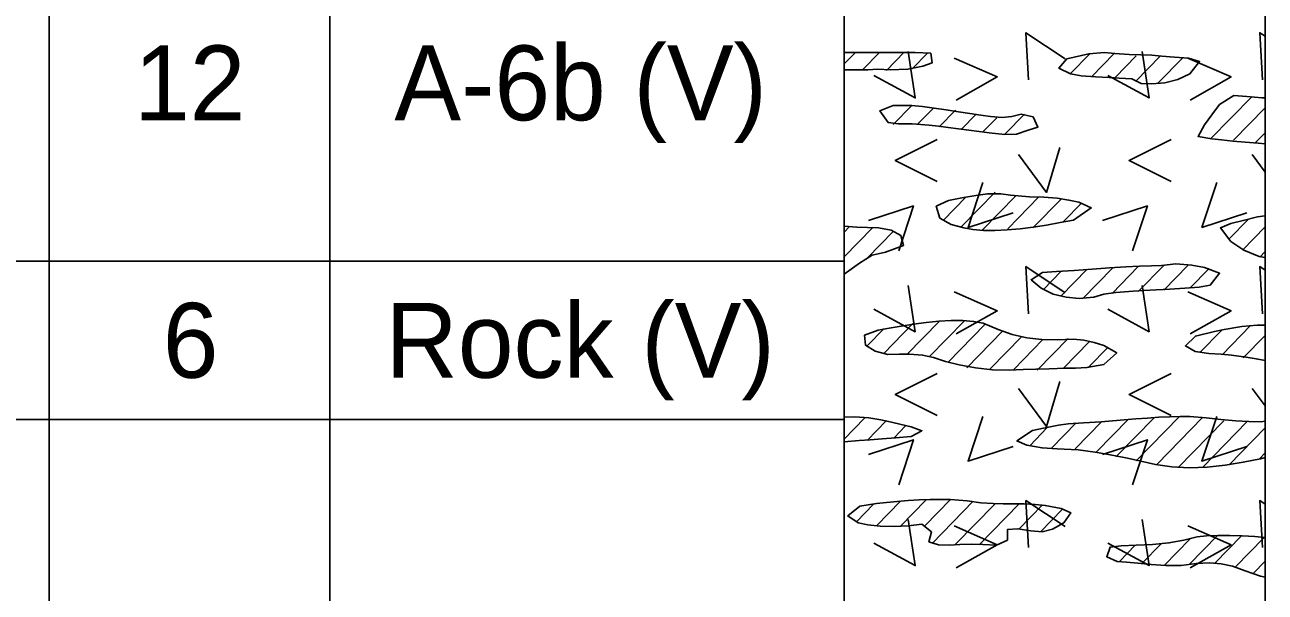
# Model space of a CAD drawing. Extents: x 0 to 0.833, y -0.32 to 0.608.
# Drawn here: x 0.7228 to 0.8333, y 0.0658 to 0.1163 of the extents above; entities that cross this region are included whole.
import ezdxf

# ---------------------------------------------------------------- set-up
doc = ezdxf.new("R2010")
doc.units = 0

msp = doc.modelspace()

# ---------------------------------------------------------------- linework, layer by layer
for points in [[(0, -0.32004), (0.83333, -0.32004), (0.83333, 0.60833), (0, 0.60833)], [(0.79583, 0.1123), (0.79676, 0.11229), (0.79792, 0.1123), (0.79882, 0.11234), (0.79992, 0.1123), (0.80151, 0.11234), (0.80282, 0.1126), (0.80367, 0.11292), (0.80354, 0.11376), (0.80216, 0.11384), (0.79583, 0.11384)], [(0.81822, 0.11165), (0.81944, 0.11159), (0.82033, 0.11155), (0.82145, 0.11148), (0.82229, 0.11107), (0.82324, 0.11103), (0.82438, 0.11113), (0.82555, 0.11142), (0.82662, 0.11192), (0.82749, 0.11302), (0.82651, 0.11332), (0.82524, 0.11342), (0.82413, 0.11349), (0.82324, 0.11359), (0.82226, 0.11361), (0.82121, 0.11364), (0.81995, 0.11373), (0.81902, 0.11384), (0.81761, 0.11371), (0.81566, 0.11326), (0.81496, 0.11242), (0.81598, 0.11193), (0.81695, 0.11176)], [(0.83305, 0.1098), (0.83171, 0.10991), (0.83054, 0.11001), (0.82925, 0.10919), (0.82857, 0.10828), (0.82792, 0.10739), (0.82735, 0.10636), (0.82858, 0.10614), (0.82945, 0.10604), (0.83045, 0.10594), (0.83155, 0.10584), (0.83272, 0.10575), (0.83333, 0.1057), (0.83333, 0.10979)], [(0.80066, 0.10749), (0.80188, 0.10749), (0.80339, 0.10736), (0.80423, 0.10726), (0.8051, 0.10715), (0.806, 0.10703), (0.80692, 0.10691), (0.80784, 0.1068), (0.80875, 0.10669), (0.81014, 0.10654), (0.81119, 0.10656), (0.81222, 0.1069), (0.81308, 0.10719), (0.81267, 0.10809), (0.8116, 0.10833), (0.81075, 0.10814), (0.80989, 0.10805), (0.80885, 0.10813), (0.80799, 0.10825), (0.80703, 0.10839), (0.806, 0.10855), (0.80492, 0.10872), (0.80384, 0.10888), (0.8028, 0.10901), (0.80182, 0.1091), (0.8002, 0.10911), (0.79901, 0.10864), (0.79974, 0.1076)], [(0.81233, 0.10099), (0.81063, 0.10111), (0.80977, 0.10124), (0.8086, 0.10125), (0.80755, 0.1011), (0.80632, 0.1009), (0.80513, 0.10066), (0.80403, 0.10014), (0.80436, 0.09908), (0.80536, 0.09851), (0.80647, 0.09821), (0.8073, 0.09806), (0.80824, 0.09799), (0.80926, 0.09798), (0.81035, 0.09803), (0.81149, 0.09813), (0.81267, 0.09828), (0.81386, 0.09846), (0.81506, 0.09868), (0.81625, 0.09891), (0.81783, 0.09999), (0.81673, 0.10049), (0.81585, 0.10069), (0.8148, 0.10085), (0.81361, 0.10095)], [(0.79583, 0.09408), (0.79719, 0.09507), (0.79831, 0.09577), (0.79951, 0.09604), (0.80111, 0.09664), (0.80086, 0.09753), (0.80002, 0.098), (0.79889, 0.0982), (0.79791, 0.09823), (0.79694, 0.09828), (0.79583, 0.09837)], [(0.83265, 0.09918), (0.83136, 0.09887), (0.83028, 0.09859), (0.82934, 0.0982), (0.83026, 0.097), (0.83142, 0.09623), (0.83279, 0.09566), (0.83333, 0.09556), (0.83333, 0.09927)], [(0.82537, 0.09502), (0.82408, 0.09487), (0.82319, 0.09482), (0.82214, 0.09479), (0.82091, 0.09475), (0.81947, 0.09466), (0.81792, 0.09454), (0.81632, 0.09442), (0.81475, 0.09433), (0.81348, 0.09423), (0.81247, 0.09359), (0.81337, 0.09283), (0.81444, 0.09232), (0.81561, 0.09204), (0.81675, 0.09193), (0.81807, 0.09204), (0.81896, 0.09232), (0.82003, 0.09246), (0.82157, 0.09258), (0.82253, 0.09264), (0.82362, 0.0927), (0.82483, 0.09276), (0.82618, 0.09283), (0.82745, 0.09294), (0.82842, 0.09311), (0.82927, 0.09417), (0.82791, 0.09468), (0.82679, 0.09488)], [(0.79885, 0.08911), (0.79763, 0.08865), (0.79773, 0.08776), (0.79859, 0.08723), (0.7997, 0.08694), (0.80074, 0.08695), (0.80165, 0.08696), (0.80281, 0.08688), (0.80377, 0.08667), (0.80486, 0.08632), (0.80606, 0.08602), (0.80751, 0.08575), (0.80905, 0.08556), (0.81052, 0.08553), (0.81177, 0.08559), (0.81289, 0.08563), (0.81408, 0.08567), (0.81553, 0.08571), (0.81642, 0.08573), (0.81745, 0.08577), (0.81897, 0.08604), (0.82011, 0.08707), (0.81896, 0.08774), (0.8181, 0.08801), (0.81717, 0.08821), (0.81626, 0.08831), (0.81479, 0.08825), (0.81343, 0.08826), (0.8121, 0.08841), (0.8108, 0.08871), (0.80953, 0.08917), (0.8082, 0.08972), (0.80736, 0.08988), (0.8064, 0.08995), (0.80536, 0.08995), (0.80427, 0.08989), (0.80314, 0.08978), (0.80201, 0.08964), (0.8009, 0.08947), (0.79984, 0.08929)], [(0.83263, 0.08956), (0.83126, 0.08942), (0.82969, 0.08916), (0.82883, 0.08898), (0.82712, 0.08857), (0.82623, 0.0877), (0.82708, 0.08721), (0.82831, 0.08703), (0.82941, 0.08696), (0.83033, 0.08687), (0.83165, 0.08669), (0.83253, 0.08655), (0.83333, 0.0864), (0.83333, 0.08955)], [(0.79583, 0.07916), (0.79715, 0.07927), (0.79814, 0.07934), (0.79922, 0.07942), (0.80039, 0.0795), (0.80179, 0.07962), (0.80275, 0.08014), (0.80179, 0.08048), (0.80091, 0.08069), (0.80003, 0.08092), (0.79909, 0.08112), (0.79803, 0.08129), (0.79677, 0.08138), (0.79583, 0.08136)], [(0.82816, 0.07691), (0.82978, 0.07708), (0.83137, 0.07733), (0.8329, 0.07764), (0.83333, 0.07775), (0.83333, 0.08099), (0.83295, 0.08095), (0.83188, 0.08098), (0.83071, 0.08103), (0.82938, 0.08113), (0.82807, 0.0813), (0.82662, 0.08142), (0.82576, 0.08142), (0.82484, 0.08139), (0.82387, 0.08134), (0.82286, 0.08127), (0.82182, 0.0812), (0.82077, 0.08111), (0.81973, 0.08103), (0.81872, 0.08095), (0.81715, 0.08086), (0.81579, 0.08077), (0.81491, 0.08063), (0.81357, 0.08036), (0.8126, 0.08015), (0.81121, 0.07923), (0.8121, 0.07886), (0.81345, 0.07862), (0.81479, 0.07853), (0.81668, 0.07843), (0.81818, 0.07823), (0.81905, 0.07808), (0.82, 0.0779), (0.82107, 0.07769), (0.82225, 0.07743), (0.82357, 0.07714), (0.82501, 0.07692), (0.82656, 0.07685)], [(0.79708, 0.07193), (0.79794, 0.07175), (0.79904, 0.07164), (0.80028, 0.0716), (0.80156, 0.07166), (0.80274, 0.07181), (0.80361, 0.07115), (0.80338, 0.07025), (0.80422, 0.06998), (0.80517, 0.06996), (0.80613, 0.07002), (0.8072, 0.07005), (0.80818, 0.07002), (0.80939, 0.06995), (0.81037, 0.07041), (0.81038, 0.07136), (0.8113, 0.07142), (0.81244, 0.07123), (0.81346, 0.07113), (0.81438, 0.07138), (0.81539, 0.07193), (0.81601, 0.07284), (0.81517, 0.07321), (0.81374, 0.07349), (0.81285, 0.07358), (0.81187, 0.07364), (0.81, 0.07364), (0.8091, 0.07366), (0.808, 0.07373), (0.80678, 0.07389), (0.8053, 0.07402), (0.80443, 0.07403), (0.80349, 0.07402), (0.80251, 0.07398), (0.80152, 0.07392), (0.80054, 0.07384), (0.79959, 0.07375), (0.7987, 0.07365), (0.79722, 0.07342), (0.79614, 0.07255)], [(0.83241, 0.07071), (0.83129, 0.07077), (0.83017, 0.07081), (0.8291, 0.07081), (0.82811, 0.07077), (0.82728, 0.07069), (0.82608, 0.07039), (0.82476, 0.07016), (0.8233, 0.07002), (0.82183, 0.06994), (0.82051, 0.06988), (0.81951, 0.06978), (0.81922, 0.06892), (0.82013, 0.0685), (0.82097, 0.06845), (0.822, 0.06835), (0.82318, 0.06822), (0.82448, 0.06813), (0.82584, 0.06815), (0.82719, 0.06832), (0.82836, 0.06839), (0.8294, 0.0683), (0.83043, 0.06807), (0.83156, 0.06768), (0.83291, 0.06719), (0.83333, 0.06711), (0.83333, 0.07063)]]:
    msp.add_lwpolyline(points, close=True)
for points in [[(0.725, 0.55417), (0.725, -0.27517)], [(0.75, 0.55417), (0.75, -0.27517)], [(0.75, 0.55417), (0.75, -0.27517)], [(0.79583, 0.55417), (0.79583, -0.27517)], [(0.725, 0.54167), (0.725, -0.27517)], [(0.83333, -0.27517), (0.83333, 0.50377)], [(0.81551, 0.11328), (0.81201, 0.11559), (0.81226, 0.1114)], [(0.83333, 0.11527), (0.83284, 0.11559), (0.83309, 0.1114)], [(0.79898, 0.11383), (0.79747, 0.11228)], [(0.79847, 0.11179), (0.80215, 0.10979), (0.80153, 0.11392)], [(0.80116, 0.11385), (0.79959, 0.11224)], [(0.8193, 0.11179), (0.82299, 0.10979), (0.82236, 0.11392)], [(0.79583, 0.11281), (0.79681, 0.11381)], [(0.80328, 0.11381), (0.80188, 0.11238)], [(0.80562, 0.11334), (0.80946, 0.11166), (0.80581, 0.10959)], [(0.8177, 0.11371), (0.81596, 0.11193)], [(0.81988, 0.11373), (0.81785, 0.11165)], [(0.82185, 0.11354), (0.81997, 0.11161)], [(0.824, 0.11353), (0.82178, 0.11125)], [(0.82601, 0.11337), (0.82378, 0.11109)], [(0.82645, 0.11334), (0.83029, 0.11166), (0.82664, 0.10959)], [(0.83217, 0.10992), (0.82844, 0.1061)], [(0.80188, 0.10915), (0.8002, 0.10743)], [(0.8038, 0.1089), (0.80237, 0.10744)], [(0.80575, 0.10869), (0.80429, 0.1072)], [(0.80758, 0.10835), (0.80627, 0.10701)], [(0.81188, 0.10833), (0.81016, 0.10658)], [(0.83333, 0.1089), (0.83052, 0.10602)], [(0.80941, 0.10802), (0.80816, 0.10674)], [(0.80412, 0.10608), (0.80038, 0.10421), (0.80412, 0.10233)], [(0.82496, 0.10608), (0.82121, 0.10421), (0.82496, 0.10233)], [(0.83333, 0.10669), (0.83245, 0.10579)], [(0.81134, 0.10474), (0.81384, 0.10137), (0.81503, 0.10537)], [(0.83217, 0.10474), (0.83333, 0.10318)], [(0.80818, 0.10225), (0.80687, 0.09825), (0.81087, 0.09956)], [(0.82901, 0.10225), (0.8277, 0.09825), (0.8317, 0.09956)], [(0.80465, 0.09887), (0.80667, 0.10095)], [(0.80626, 0.0983), (0.80928, 0.1014)], [(0.80809, 0.09797), (0.81111, 0.10107)], [(0.81041, 0.09814), (0.81318, 0.10097)], [(0.81264, 0.09821), (0.81518, 0.10081)], [(0.80069, 0.09617), (0.802, 0.10017), (0.798, 0.09886)], [(0.81536, 0.09878), (0.81699, 0.10045)], [(0.82152, 0.09617), (0.82284, 0.10017), (0.81884, 0.09886)], [(0.8301, 0.09721), (0.83184, 0.09899)], [(0.7963, 0.09833), (0.79583, 0.09784)], [(0.79834, 0.0982), (0.79583, 0.09563)], [(0.79786, 0.0955), (0.80023, 0.09792)], [(0.83131, 0.09623), (0.83333, 0.09831)], [(0.70417, 0.09525), (0.725, 0.09525)], [(0.725, 0.09525), (0.75, 0.09525)], [(0.75, 0.09525), (0.79583, 0.09525)], [(0.83285, 0.09561), (0.83333, 0.0961)], [(0.81551, 0.09244), (0.81201, 0.09476), (0.81226, 0.09057)], [(0.81519, 0.09439), (0.81354, 0.0927)], [(0.81514, 0.09213), (0.81748, 0.09453)], [(0.81709, 0.09191), (0.81974, 0.09463)], [(0.8197, 0.09237), (0.82203, 0.09477)], [(0.82202, 0.09253), (0.8243, 0.09487)], [(0.82431, 0.09267), (0.82644, 0.09486)], [(0.82663, 0.09283), (0.82834, 0.09458)], [(0.83333, 0.09443), (0.83284, 0.09476), (0.83309, 0.09057)], [(0.79847, 0.09096), (0.80215, 0.08896), (0.80153, 0.09309)], [(0.8193, 0.09096), (0.82299, 0.08896), (0.82236, 0.09309)], [(0.80562, 0.09251), (0.80946, 0.09082), (0.80581, 0.08876)], [(0.82645, 0.09251), (0.83029, 0.09082), (0.82664, 0.08876)], [(0.79933, 0.08699), (0.80195, 0.08968)], [(0.80142, 0.08692), (0.8043, 0.08987)], [(0.80653, 0.08994), (0.8034, 0.08673)], [(0.80506, 0.08622), (0.8084, 0.08964)], [(0.83203, 0.08951), (0.82949, 0.08691)], [(0.79938, 0.08925), (0.79786, 0.0877)], [(0.80997, 0.08904), (0.80675, 0.08574)], [(0.81164, 0.08854), (0.80884, 0.08567)], [(0.82751, 0.0871), (0.82945, 0.08908)], [(0.83138, 0.08663), (0.83333, 0.08863)], [(0.81353, 0.08826), (0.81094, 0.08561)], [(0.81303, 0.08554), (0.81579, 0.08837)], [(0.81534, 0.0857), (0.81768, 0.08809)], [(0.8176, 0.0858), (0.81934, 0.08758)], [(0.83333, 0.08642), (0.83333, 0.08642)], [(0.80412, 0.08525), (0.80038, 0.08337), (0.80412, 0.0815)], [(0.82496, 0.08525), (0.82121, 0.08337), (0.82496, 0.0815)], [(0.81134, 0.08391), (0.81384, 0.08053), (0.81503, 0.08453)], [(0.83217, 0.08391), (0.83333, 0.08235)], [(0.70417, 0.08114), (0.725, 0.08114)], [(0.725, 0.08114), (0.75, 0.08114)], [(0.75, 0.08114), (0.79583, 0.08114)], [(0.79765, 0.08127), (0.79583, 0.0794)], [(0.7996, 0.08105), (0.79786, 0.07927)], [(0.80818, 0.08142), (0.80687, 0.07742), (0.81087, 0.07873)], [(0.8143, 0.07859), (0.8165, 0.08084)], [(0.8164, 0.07852), (0.81879, 0.08098)], [(0.81829, 0.07825), (0.82114, 0.08117)], [(0.82004, 0.07783), (0.82346, 0.08133)], [(0.82569, 0.08141), (0.82184, 0.07747)], [(0.82775, 0.08131), (0.8237, 0.07716)], [(0.82964, 0.08104), (0.82557, 0.07686)], [(0.82901, 0.08142), (0.8277, 0.07742), (0.8317, 0.07873)], [(0.83173, 0.08097), (0.82774, 0.07688)], [(0.8013, 0.08058), (0.80027, 0.07952)], [(0.81392, 0.08042), (0.81235, 0.07881)], [(0.83333, 0.08039), (0.83012, 0.0771)], [(0.80069, 0.07534), (0.802, 0.07934), (0.798, 0.07802)], [(0.82152, 0.07534), (0.82284, 0.07934), (0.81884, 0.07802)], [(0.83281, 0.07764), (0.83333, 0.07818)], [(0.80534, 0.07404), (0.80299, 0.07163)], [(0.79844, 0.07361), (0.79691, 0.07204)], [(0.79871, 0.07167), (0.80085, 0.07386)], [(0.80083, 0.07163), (0.80311, 0.07397)], [(0.80367, 0.07011), (0.80732, 0.07386)], [(0.80571, 0.07), (0.80924, 0.07361)], [(0.81142, 0.07363), (0.80785, 0.06997)], [(0.81141, 0.0714), (0.81348, 0.07353)], [(0.81551, 0.07161), (0.81201, 0.07392), (0.81226, 0.06973)], [(0.81528, 0.07316), (0.81331, 0.07114)], [(0.83333, 0.0736), (0.83284, 0.07392), (0.83309, 0.06973)], [(0.79847, 0.07013), (0.80215, 0.06813), (0.80153, 0.07225)], [(0.8193, 0.07013), (0.82299, 0.06813), (0.82236, 0.07225)], [(0.80562, 0.07167), (0.80946, 0.06999), (0.80581, 0.06793)], [(0.82645, 0.07167), (0.83029, 0.06999), (0.82664, 0.06793)], [(0.82909, 0.07081), (0.82656, 0.06822)], [(0.82885, 0.06835), (0.83122, 0.07078)], [(0.82035, 0.06849), (0.82176, 0.06994)], [(0.82233, 0.06831), (0.82408, 0.0701)], [(0.82433, 0.06814), (0.82666, 0.07053)], [(0.83325, 0.07064), (0.83065, 0.06798)], [(0.83333, 0.06852), (0.83227, 0.06742)]]:
    msp.add_lwpolyline(points)

# ---------------------------------------------------------------- texts
for s, height, p in [('12', 0.006667, (0.73257, 0.10779)), ('A-6b (V)', 0.006667, (0.75575, 0.10779)), ('Rock (V)', 0.006667, (0.75497, 0.08486)), ('6', 0.00667, (0.73512, 0.08486))]:
    msp.add_text(s, height=height).set_placement(p)

doc.saveas('drawing.dxf')
